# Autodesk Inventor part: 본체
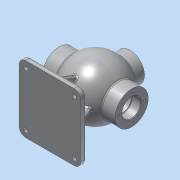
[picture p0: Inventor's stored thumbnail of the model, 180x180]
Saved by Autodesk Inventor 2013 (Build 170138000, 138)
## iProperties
Created: 2018-06
Part Number: 본체
Material: 알루미늄 6061
Document SubType Name: Modeling
Designer: Administrator
Density: 2.71 g/cm^3
Mass: 1509.59 g
Surface Area: 1153.86 cm^2
Volume: 557.044 cm^3
Author: Administrator
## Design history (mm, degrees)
sketch "스케치1"
  geometry: L1 (53, 0)-(43, 0); L2 (-43, 0)-(-53, 0); A1 r 53 centre (0, 0) between (53, 0) and (-53, 0); A2 r 43 centre (0, 0) between (43, 0) and (-43, 0); 2 further points
  constraints: 4 end point, 4 point on circle, 3 coincident, 2 centre point, 2 horizontal
  dimensions: "d4" = 106 diameter of A1; "d5" = 86 diameter of A2; "d6" = 10 distance of L1.start L1.end; "d7" = 10 distance of L2.start L2.end
revolve "회전1" sketch "스케치1" stored, may be unused: angle "d8" = 90 deg
node "작업 평면1"
sketch "스케치2"
  geometry: L1 (-57.5, -62.5)-(57.5, -62.5); L2 (57.5, -62.5)-(57.5, 62.5); L3 (57.5, 62.5)-(-57.5, 62.5); L4 (-57.5, 62.5)-(-57.5, -62.5); L5 (-57.5, -62.5)-(57.5, 62.5); L6 (57.5, -62.5)-(-57.5, 62.5); 1 further point
  constraints: 12 end point, 2 midpoint, 2 parallel, 1 horizontal, 1 perpendicular
  dimensions: "d10" = 115 distance of L3.end L2.end; "d11" = 125 distance of L2.end L1.end
extrude "돌출1" join sketch "스케치2" distance "d12" = 10; taper "d13" = 0 deg
sketch "스케치3"
  geometry: L1 (57.5, 62.5)-(-57.5, 62.5) reference; L2 (-4, 52.5)-(4, 52.5); L3 (4, 52.5)-(4, -52.5); L4 (4, -52.5)-(-4, -52.5); L5 (-4, -52.5)-(-4, 52.5); L6 (-4, 52.5)-(4, -52.5); L7 (4, 52.5)-(-4, -52.5); 1 further point
  constraints: 12 end point, 2 midpoint, 2 parallel, 1 horizontal, 1 perpendicular
  dimensions: "d14" = 8 distance of L3.end L4.end; "d15" = 10 distance between parallel lines of L1 L2
extrude "돌출2" join sketch "스케치3" stored distance "d16" = 0; taper "d17" = 0 deg
sketch "스케치4"
  geometry: L1 (57.5, -85)-(57.5, -75) reference; L2 (-57.5, -85)-(-57.5, -75) reference; L3 (-57.5, -75)-(-4, -75) reference; L4 (-4, -75)-(-4, -52.849) reference; L5 (4, -52.849)-(4, -75) reference; L6 (4, -75)-(57.5, -75) reference; L7 (57.5, -75)-(57.5, -85) reference; L8 (57.5, -85)-(-57.5, -85) reference; L9 (47.5, -75)-(35.051, -44.187); C1 r 43 at (0, 0) reference; A1 r 53 centre (0, 0) between (4, -52.849) and (-4, -52.849) reference; 1 further point
  constraints: 2 end point, 1 point on line
  dimensions: "d20" = 10 distance from line of L1 L9.start; "d21" = 22 deg angle of L1 L9
feature "리브1" sketch "스케치4" dims "d22" = 1, "d23" = 8, "d24" = 0, "d25" = 0, "d26" = 1, "d27" = 1
node "작업 평면2"
sketch "스케치5"
  geometry: C1 r 31 at (0, 0); 1 further point
  constraints: 1 centre point, 1 coincident
  dimensions: "d29" = 62 diameter of C1
extrude "돌출3" join sketch "스케치5" stored distance "d30" = 10; taper "d31" = 0 deg
hole "구멍1" diameter "d34" = 35; stored, may be unused: countersink angle "d38" = 90 deg, drill point angle "d40" = 0 deg; dims "d35" = 6, "d36" = 4, "d37" = 2, "d39" = 16, "d41" = 10, "d42" = 10
sketch "스케치6"
  geometry: C1 r 17.5 at (0, 0) reference; 1 further point
  constraints: 1 coincident
hole "구멍2" sketch "스케치6" at (0, 0) diameter "d43" = 35; stored, may be unused: countersink angle "d47" = 90 deg, drill point angle "d49" = 0 deg; dims "d44" = 6, "d45" = 37, "d46" = 1.75, "d48" = 16
hole "구멍3" diameter "d52" = 35; stored, may be unused: countersink angle "d56" = 90 deg, drill point angle "d58" = 0 deg; dims "d50" = 10, "d51" = 10, "d53" = 6, "d54" = 37, "d55" = 1.75, "d57" = 16
node "작업 평면3"
sketch "스케치7"
  geometry: C1 r 27 at (0, 0); 1 further point
  constraints: 1 centre point, 1 coincident
  dimensions: "d60" = 54 diameter of C1
extrude "돌출4" join sketch "스케치7" stored distance "d61" = 10; taper "d62" = 0 deg
hole "구멍4" diameter "d65" = 26; stored, may be unused: countersink angle "d69" = 90 deg, drill point angle "d71" = 0 deg; dims "d63" = 10, "d64" = 10, "d66" = 6, "d67" = 37, "d68" = 1.75, "d70" = 16
sketch "스케치8"
  geometry: C1 r 17.5 at (0, 0) reference; 1 further point
  constraints: 1 vertical alignment
  dimensions: "d72" = 24 distance of C1.centre point (0, 24)
hole "구멍5" sketch "스케치8" at (0, 24) diameter "d73" = 3.242; stored, may be unused: countersink angle "d77" = 90 deg, drill point angle "d79" = 118 deg; dims "d74" = 16, "d75" = 37, "d76" = 1.75, "d78" = 19
sketch "스케치9"
  geometry: C1 r 17.5 at (0, 0) reference; 1 further point
  constraints: 1 vertical alignment
  dimensions: "d83" = 22.5 distance of C1.centre point (0, 22.5)
hole "구멍6" sketch "스케치9" at (0, 22.5) diameter "d84" = 3.242; stored, may be unused: countersink angle "d88" = 90 deg, drill point angle "d90" = 118 deg; dims "d85" = 12, "d86" = 37, "d87" = 1.75, "d89" = 15
sketch "스케치10"
  geometry: C1 r 13 at (0, 0) reference; 1 further point
  constraints: 1 vertical alignment
  dimensions: "d94" = 20 distance of C1.centre point (0, 20)
hole "구멍7" sketch "스케치10" at (0, 20) diameter "d95" = 3.242; stored, may be unused: countersink angle "d99" = 90 deg, drill point angle "d101" = 118 deg; dims "d96" = 9, "d97" = 37, "d98" = 1.75, "d100" = 11
feature "면 기울기2" dims angle "d102" = 22 deg
fillet "모깎기1" dims "d103" = 12
fillet "모깎기2" dims "d107" = 3
fillet "모깎기3" dims "d108" = 3
chamfer "모따기1" distance "d109" = 1; stored, may be unused: second distance "d110" = 2, angle "d111" = 45 deg
sketch "스케치11"
  geometry: A1 r 9 centre (-45.5, 50.5) between (-45.5, 59.5) and (-54.5, 50.5) reference; A2 r 9 centre (-45.5, -50.5) between (-54.5, -50.5) and (-45.5, -59.5) reference; A3 r 9 centre (45.5, -50.5) between (45.5, -59.5) and (54.5, -50.5) reference; A4 r 9 centre (45.5, 50.5) between (54.5, 50.5) and (45.5, 59.5) reference; 5 further points
  constraints: 4 coincident
hole "구멍8" sketch "스케치11" at (45.5, 50.5), (45.5, -50.5), (-45.5, -50.5), (-45.5, 50.5) diameter "d112" = 8; stored, may be unused: countersink angle "d116" = 90 deg, drill point angle "d118" = 118 deg; dims "d113" = 8, "d114" = 12, "d115" = 3, "d117" = 11
node "작업 평면5"
sketch "스케치13"
  geometry: L1 (-27, 0)-(27, 0) reference; 2 further points
  constraints: 1 vertical alignment, 1 other
  dimensions: "d122" = 10 distance from line of L1 point (0, -10)
feature "엠보싱2" sketch "스케치13" dims "d123" = 0.5, "d124" = 0
node "솔리드1"
mirror "대칭1"
mirror "대칭2"
pattern_circular "원형 패턴1" dims angle "d81" = 360 deg
pattern_circular "원형 패턴2" dims angle "d92" = 360 deg
pattern_circular "원형 패턴3" dims angle "d105" = 360 deg
node "절단 모서리 투영1"
other parameters: "d9" = -85, "d28" = 68
